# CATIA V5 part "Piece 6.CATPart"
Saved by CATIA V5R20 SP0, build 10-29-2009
Part number: Piece 6
Bounding box of the stored display mesh (mm): x -135.74 to 63.955, y 0.429 to 14.429, z 0 to 4
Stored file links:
  G:\Khaled_CFAO_2011\SIL\SIL_GR1\blaboucarri\Khaled\CAD_CATIA\Piece 6.CATPart
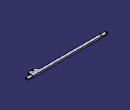
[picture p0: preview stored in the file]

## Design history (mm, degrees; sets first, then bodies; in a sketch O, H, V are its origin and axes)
Parameters
  `longueur piece` = 200 mm
  `epaisseur piece` = 4 mm
  `rayon trou ` = 1.5 mm
  `éloignement trou bord ` = 1 mm
  `distance trou surélevé` = 160 mm
  `longueur trou surélevé` = 20 mm
  `distance bord trou surélevé` = 20 mm
  `largeur trou suélevé` = 7 mm
  `largeur piece` = 7 mm
  `longueur poche ` = 15 mm
  `largeur poche` = 1 mm
  `longueur poche surélevée` = 20 mm
  `largeur poche surélevé` = 2 mm
Body1 (main body)
  Sketch1 on xy-plane, origin (0, 0, 0), H (1, 0, 0), V (0, 1, 0)
    line L1 (-131.3434, 14.4295) -> (59.1101, 14.4295)
    point P1 (64.0835, 14.4295)
    point P2 (64.0835, 7.4295)
    line L2 (59.8763, 7.4295) -> (53.4777, 7.4295)
    point P3 (44.0835, 7.4295)
    point P4 (48.9825, 0.4295)
    line L3 (45.8145, 0.4295) -> (32.5943, 0.4295)
    point P5 (28.9825, 0.4295)
    point P6 (24.0835, 7.4295)
    line L4 (24.6442, 7.4295) -> (-130.9087, 7.4295)
    point P7 (-135.9165, 7.4295)
    circle A1 centre (38.7731, 2.9295) radius 1.5
    point P8 (38.7731, 2.9295)
    circle A2 centre (62.0766, 10.9295) radius 1.5
    point P9 (62.0766, 10.9295)
    circle A3 centre (-133.6585, 10.9295) radius 1.5
    point P10 (-133.6585, 10.9295)
    arc A4 centre (59.1101, 9.4487) radius 4.9808 from (63.9549, 10.6045) to (59.1101, 14.4295) ccw
    point P11 (64.0909, 9.4487)
    arc A5 centre (59.8763, 11.6367) radius 4.2073 from (59.8763, 7.4295) to (63.9549, 10.6045) ccw
    arc A6 centre (-131.3434, 9.8564) radius 4.5731 from (-131.3434, 14.4295) to (-135.7397, 11.1154) ccw
    point P17 (-135.9165, 9.8564)
    arc A7 centre (-130.9087, 12.4384) radius 5.0089 from (-130.9087, 7.4295) to (-135.7397, 11.1154) cw
    arc A8 centre (24.6442, 3.0912) radius 4.3383 from (28.9476, 3.6404) to (24.6442, 7.4295) ccw
    arc A9 centre (53.4777, 2.9343) radius 4.4952 from (53.4777, 7.4295) to (49.0009, 3.3401) ccw
    arc A10 centre (45.8145, 3.6289) radius 3.1994 from (49.0009, 3.3401) to (45.8145, 0.4295) cw
    arc A11 centre (32.5943, 4.1057) radius 3.6762 from (28.9476, 3.6404) to (32.5943, 0.4295) ccw
    point P31 (-135.7397, 11.1154)
    point P32 (-135.7397, 11.1154)
    point P33 (64.0304, 10.2193)
    point P34 (63.9549, 10.6045)
    point P35 (63.9549, 10.6045)
    radius A2 = 1.5 {= `rayon trou `}
    radius A3 = 1.5 {= `rayon trou `}
    radius A1 = 1.5 {= `rayon trou `}
    distance P1 P2 = 7 {= `largeur piece`}
    radius A4 = 4.9808
    distance P2 P3 = 20 {= `distance bord trou surélevé`}
    radius A5 = 4.2073
    radius A6 = 4.5731
    distance P6 P7 = 160 {= `distance trou surélevé`}
    radius A7 = 5.0089
    radius A8 = 4.3383
    radius A9 = 4.4952
    distance P4 P5 = 20 {= `longueur trou surélevé`}
    radius A10 = 3.1994
    radius A11 = 3.6762
    distance P10 P17 = 2.5 {= `rayon trou ` +`éloignement trou bord `}
    distance P9 P11 = 2.5 {= `éloignement trou bord ` +`rayon trou `}
    distance P8 L3 = 2.5 {= `rayon trou ` +`éloignement trou bord `}
    distance L4 L3 = 7 {= `largeur trou suélevé`}
    distance P10 L4 = 3.5 {= `largeur piece` /2}
    distance P9 L1 = 3.5 {= `largeur piece` /2}
    horizontal: L1 H, L2 H, L3 H, L4 H
    coincidence: P6 L2, L1 P1, L2 P2, L4 P7, L4 P6, L2 P3, L3 P4, L3 P5, A6 P31, P17 A6, P32 P31, P11 A4, P34 P35
    tangency: A4 L1, A5 L2, A6 L1, A7 L4, A8 L4, A9 L2, A10 L3, A10 A9, A11 L3, A11 A8
  Sketch2 on xy-plane, origin (0, 0, 0), H (1, 0, 0), V (0, 1, 0)
  Pad1: profile Sketch1, direction (0, 0, 1), length 4 {= `epaisseur piece`}
  Sketch3 on zx-plane, origin (0, 0, 0), H (0, 0, 1), V (1, 0, 0)
    line L1 (3, 64.0896) -> (4, 64.0896)
    line L2 (4, 64.0896) -> (4, 49.0896)
    line L3 (4, 49.0896) -> (3, 49.0896)
    line L4 (3, 49.0896) -> (3, 64.0896)
    reference projected line E1 (4, 59.1088) -> (4, -131.3373) from edge [face of Pad1 from Sketch1.L1 | end face of Pad1]
    point P5 (0, 64.0896)
    line L5 (0, 64.0896) -> (1, 64.0896)
    line L6 (1, 64.0896) -> (1, 49.0896)
    line L7 (1, 49.0896) -> (0, 49.0896)
    line L8 (0, 49.0896) -> (0, 64.0896)
    point P7 (1, 49.0896)
    point P9 (0, -120.9104)
    line L9 (0, -120.9104) -> (1, -120.9104)
    line L10 (1, -120.9104) -> (1, -135.9104)
    line L11 (1, -135.9104) -> (0, -135.9104)
    line L12 (0, -135.9104) -> (0, -120.9104)
    point P13 (4, -120.9104)
    line L13 (4, -120.9104) -> (3, -120.9104)
    line L14 (3, -120.9104) -> (3, -135.9104)
    line L15 (3, -135.9104) -> (4, -135.9104)
    line L16 (4, -135.9104) -> (4, -120.9104)
    point P15 (3, -135.9104)
    reference projected line E2 (0, 64.0896) -> (4, 64.0896) from edge [face of Pad1 from Sketch1.A4 | face of Pad1]
    reference projected line E3 (0, -135.9104) -> (4, -135.9104) from edge [face of Pad1 | face of Pad1 from Sketch1.A6]
    reference projected line E4 (4, 59.1088) -> (4, -131.3373) from edge [face of Pad1 from Sketch1.L1 | end face of Pad1]
    length L2 = 15 {= `longueur poche `}
    length L1 = 1 {= `largeur poche`}
    distance L2 E1 = 0
    length L5 = 1 {= `largeur poche`}
    distance E2 L5 = 0
    distance L11 E3 = 0
    length L12 = 15 {= `longueur poche `}
    length L9 = 1 {= `largeur poche`}
    length L13 = 1 {= `largeur poche`}
    distance L16 E4 = 0
    horizontal: L1 H, L3 H, L5 H, L7 H, L9 H, L11 H, L13 H, L15 H
    vertical: L2 V, L4 V, L6 V, L8 V, L10 V, L12 V, L14 V, L16 V
    coincidence: P5 V, P5 L1, P7 L3, P9 V, P13 L9, P15 L11
  Pocket1: profile Sketch3, direction (0, 1, 0), length 19
  Sketch4 on face of Pad1 from Sketch1.L3, origin (0, 0.4295, 0), H (1, 0, 0), V (0, 0, 1)
    line L1 (24.1304, 3) -> (54.1304, 3)
    line L2 (54.1304, 3) -> (54.1304, 1)
    line L3 (54.1304, 1) -> (24.1304, 1)
    line L4 (24.1304, 1) -> (24.1304, 3)
    reference projected line E1 (59.8823, 3) -> (54.0896, 3) from edge [face of Pocket1 from Sketch3.L4 | face of Pad1 from Sketch1.L2]
    length L1 = 30 {= `longueur poche surélevée` +`longueur poche surélevée` /2}
    length L2 = 2 {= `largeur poche surélevé`}
    distance E1 L1 = 0
    horizontal: L1 H, L3 H
    vertical: L2 V, L4 V
  Pocket2: profile Sketch4, direction (0, 1, 0), length 7 {= `largeur trou suélevé`}
  Point1: type Center, Curve edge [face of Pad1 from Sketch1.A3 | face of Pocket1 from Sketch3.L14]
  Line1: type Normal, RefPoint Point1, RefSkin face of Pocket1 from Sketch3.L14, Start 0, End 20
  Plane1: type Normal, Curve Line1, RefPoint Point1
  Plane2: type Offset, RefPlane Plane1, Offset 1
